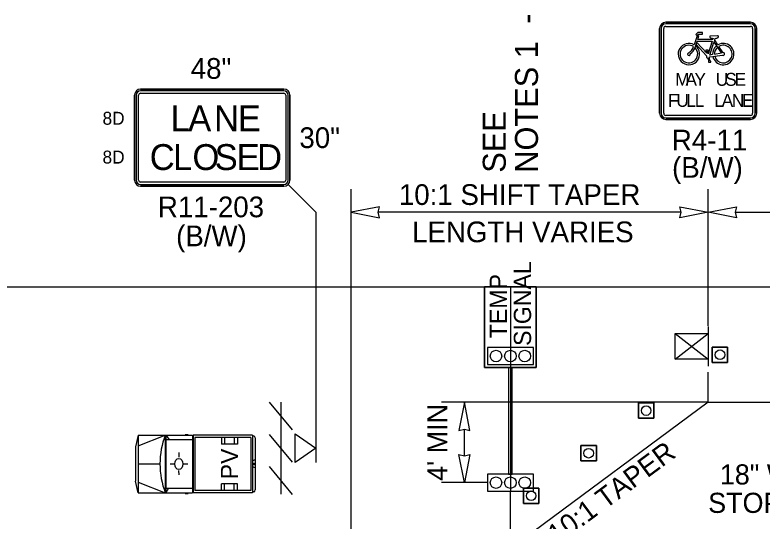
# Model space of a CAD drawing. Extents: x 99977 to 100176, y 99905 to 100011.
# Drawn here: x 100022.4 to 100024.999, y 99977.126 to 99978.886 of the extents above; entities that cross this region are included whole.
import ezdxf

# ---------------------------------------------------------------- set-up
doc = ezdxf.new("R2010")
doc.units = 0
for name, color, linetype in [('RD_ED_ShoulderPavedEdge', 7, 'Continuous'), ('RD_MK_LineEdgeWhite', 7, 'Continuous'), ('TR_SN_ConstructionSigns', 7, 'Continuous'), ('TR_WZ_BarricadeType3', 7, 'Continuous'), ('TR_WZ_PortableSignMount5ftMinBlk-Wht', 7, 'Continuous'), ('TR_WZ_PortableSignMountBlk-Wht', 7, 'Continuous'), ('TR_WZ_ProtectiveVehicle', 7, 'Continuous'), ('TR_WZ_TempSignal', 7, 'Continuous'), ('TR_WZ_TrafficCone', 7, 'Continuous'), ('TR_WZ_WorkZoneDetails', 7, 'Continuous'), ('TR_WZ_WorkZoneTextCurrent', 7, 'Continuous')]:
    doc.layers.add(name, color=color, linetype=linetype)

msp = doc.modelspace()

# ---------------------------------------------------------------- linework, layer by layer
at = {"layer": 'RD_ED_ShoulderPavedEdge'}
msp.add_line((100035.6424, 99977.9393), (100020.3, 99977.9393), dxfattribs=at)
at = {"layer": 'RD_MK_LineEdgeWhite'}
for q in [(100023.5692, 99976.6193), (100035.6425, 99977.5393)]:
    msp.add_line((100024.8112, 99977.5393), q, dxfattribs=at)
at = {"layer": 'TR_SN_ConstructionSigns'}
for p, q in [((100024.6423, 99978.5435), (100024.6423, 99978.8388)), ((100024.6423, 99978.8388), (100024.6423, 99978.5435)), ((100024.6423, 99978.8388), (100024.6423, 99978.5435)), ((100024.648, 99978.8388), (100024.648, 99978.5435)), ((100024.6564, 99978.5435), (100024.6564, 99978.8388)), ((100024.6634, 99978.8599), (100024.9588, 99978.8599)), ((100024.9588, 99978.8599), (100024.6634, 99978.8599)), ((100024.9588, 99978.8599), (100024.6634, 99978.8599)), ((100024.9588, 99978.8543), (100024.6634, 99978.8543)), ((100024.6634, 99978.8458), (100024.9588, 99978.8458)), ((100024.9658, 99978.8388), (100024.9658, 99978.5435)), ((100024.9742, 99978.5435), (100024.9742, 99978.8388)), ((100024.9798, 99978.8388), (100024.9798, 99978.5435)), ((100024.9798, 99978.5435), (100024.9798, 99978.8388)), ((100024.9798, 99978.5435), (100024.9798, 99978.8388)), ((100024.7728, 99978.8131), (100024.7624, 99978.782)), ((100024.7751, 99978.8247), (100024.7681, 99978.8178)), ((100024.7681, 99978.8178), (100024.7728, 99978.8131)), ((100024.775, 99978.8006), (100024.7792, 99978.8131)), ((100024.7916, 99978.8247), (100024.7751, 99978.8247)), ((100024.7752, 99978.8171), (100024.7774, 99978.8192)), ((100024.7792, 99978.8131), (100024.7752, 99978.8171)), ((100024.7774, 99978.8192), (100024.7916, 99978.8192)), ((100024.7916, 99978.8192), (100024.7916, 99978.8247)), ((100024.8435, 99978.8135), (100024.8186, 99978.8118)), ((100024.7676, 99978.7784), (100024.7692, 99978.7831)), ((100024.7692, 99978.7831), (100024.7715, 99978.7902)), ((100024.7692, 99978.7831), (100024.8058, 99978.7433)), ((100024.7715, 99978.7902), (100024.7728, 99978.794)), ((100024.8062, 99978.7526), (100024.7715, 99978.7902)), ((100024.7728, 99978.794), (100024.8254, 99978.794)), ((100024.8276, 99978.8006), (100024.775, 99978.8006)), ((100024.8254, 99978.794), (100024.811, 99978.7507)), ((100024.8164, 99978.7462), (100024.8312, 99978.7904)), ((100024.8288, 99978.804), (100024.8276, 99978.8006)), ((100024.8338, 99978.7983), (100024.8312, 99978.7904)), ((100024.8312, 99978.7904), (100024.8396, 99978.778)), ((100024.8338, 99978.7983), (100024.8357, 99978.8041)), ((100024.845, 99978.7818), (100024.8338, 99978.7983)), ((100024.7676, 99978.7784), (100024.7653, 99978.7717)), ((100024.8115, 99978.7633), (100024.8027, 99978.7633)), ((100024.8049, 99978.76), (100024.8062, 99978.7526)), ((100024.811, 99978.7507), (100024.8093, 99978.76)), ((100024.8093, 99978.76), (100024.8115, 99978.76)), ((100024.8115, 99978.76), (100024.8115, 99978.7633)), ((100024.8396, 99978.778), (100024.8433, 99978.7725)), ((100024.8433, 99978.7725), (100024.8571, 99978.7522)), ((100024.8636, 99978.7544), (100024.8487, 99978.7763)), ((100024.8101, 99978.7352), (100024.8137, 99978.7244)), ((100024.8183, 99978.7244), (100024.8143, 99978.7366)), ((100024.816, 99978.7395), (100024.8273, 99978.7411)), ((100024.8264, 99978.7477), (100024.8164, 99978.7462)), ((100024.8273, 99978.7411), (100024.8338, 99978.7421)), ((100024.8571, 99978.7522), (100024.8329, 99978.7486)), ((100024.8338, 99978.7421), (100024.8601, 99978.746)), ((100024.8137, 99978.7244), (100024.8119, 99978.7244)), ((100024.8119, 99978.7244), (100024.8119, 99978.7211)), ((100024.8119, 99978.7211), (100024.8207, 99978.7211)), ((100024.8207, 99978.7244), (100024.8183, 99978.7244)), ((100024.8207, 99978.7211), (100024.8207, 99978.7244)), ((100022.8369, 99978.6276), (100023.3348, 99978.6276)), ((100023.3348, 99978.6276), (100022.8369, 99978.6276)), ((100023.3348, 99978.6276), (100022.8369, 99978.6276)), ((100022.8159, 99978.3112), (100022.8159, 99978.6065)), ((100022.8159, 99978.6065), (100022.8159, 99978.3112)), ((100022.8159, 99978.6065), (100022.8159, 99978.3112)), ((100022.8215, 99978.6065), (100022.8215, 99978.3112)), ((100022.8299, 99978.3112), (100022.8299, 99978.6065)), ((100023.3348, 99978.622), (100022.8369, 99978.622)), ((100022.8369, 99978.6135), (100023.3348, 99978.6135)), ((100023.3418, 99978.6065), (100023.3418, 99978.3112)), ((100023.3502, 99978.3112), (100023.3502, 99978.6065)), ((100023.3559, 99978.6065), (100023.3559, 99978.3112)), ((100023.3559, 99978.3112), (100023.3559, 99978.6065)), ((100023.3559, 99978.3112), (100023.3559, 99978.6065)), ((100024.9588, 99978.5364), (100024.6634, 99978.5364)), ((100024.6634, 99978.528), (100024.9588, 99978.528)), ((100024.9588, 99978.5224), (100024.6634, 99978.5224)), ((100024.6634, 99978.5224), (100024.9588, 99978.5224)), ((100024.6634, 99978.5224), (100024.9588, 99978.5224)), ((100023.3348, 99978.3042), (100022.8369, 99978.3042)), ((100022.8369, 99978.2957), (100023.3348, 99978.2957)), ((100023.3348, 99978.2901), (100022.8369, 99978.2901)), ((100022.8369, 99978.2901), (100023.3348, 99978.2901)), ((100022.8369, 99978.2901), (100023.3348, 99978.2901))]:
    msp.add_line(p, q, dxfattribs=at)
msp.add_lwpolyline([(100024.8027, 99978.7633), (100024.8027, 99978.76), (100024.8049, 99978.76)], dxfattribs=at)
for centre, radius, start, end in [((100024.6634, 99978.8388), 0.0211, 90, 180), ((100024.6634, 99978.8388), 0.0211, 90, 180), ((100024.6634, 99978.8388), 0.0211, 90, 180), ((100024.6634, 99978.8388), 0.0155, 90, 180), ((100024.6634, 99978.8388), 0.00703, 90, 180), ((100024.9588, 99978.8388), 0.0211, 0, 90), ((100024.9588, 99978.8388), 0.0211, 0, 90), ((100024.9588, 99978.8388), 0.0211, 0, 90), ((100024.9588, 99978.8388), 0.0155, 0, 90), ((100024.9588, 99978.8388), 0.00703, 0, 90), ((100024.8186, 99978.8096), 0.00219, 89.3854, 243.6828), ((100024.8438, 99978.8102), 0.00329, 294.5519, 96.4128), ((100024.7441, 99978.7495), 0.0373, 60.5529, 50.868), ((100024.8636, 99978.7495), 0.0373, 192.9622, 119.9648), ((100024.7441, 99978.7495), 0.0307, 58.1532, 46.1649), ((100024.8636, 99978.7495), 0.0373, 130.0889, 182.8379), ((100024.8636, 99978.7495), 0.0307, 131.3616, 181.6359), ((100024.8636, 99978.7495), 0.0307, 193.937, 119.0598), ((100024.7441, 99978.7495), 0.00493, 105.257, 14.3233), ((100024.8106, 99978.7407), 0.00548, 151.1744, 264.8566), ((100024.8106, 99978.7407), 0.00548, 312.0053, 347.2932), ((100024.8636, 99978.7495), 0.00493, 225.1095, 90.4672), ((100022.8369, 99978.6065), 0.0211, 90, 180), ((100022.8369, 99978.6065), 0.0211, 90, 180), ((100022.8369, 99978.6065), 0.0211, 90, 180), ((100023.3348, 99978.6065), 0.0211, 0, 90), ((100023.3348, 99978.6065), 0.0211, 0, 90), ((100023.3348, 99978.6065), 0.0211, 0, 90), ((100022.8369, 99978.6065), 0.0155, 90, 180), ((100022.8369, 99978.6065), 0.00703, 90, 180), ((100023.3348, 99978.6065), 0.0155, 0, 90), ((100023.3348, 99978.6065), 0.00703, 0, 90), ((100024.6634, 99978.5435), 0.0211, 180, 270), ((100024.6634, 99978.5435), 0.0211, 180, 270), ((100024.6634, 99978.5435), 0.0211, 180, 270), ((100024.6634, 99978.5435), 0.0155, 180, 270), ((100024.6634, 99978.5435), 0.00703, 180, 270), ((100024.9588, 99978.5435), 0.0211, 270, 0), ((100024.9588, 99978.5435), 0.0211, 270, 0), ((100024.9588, 99978.5435), 0.0155, 270, 0), ((100024.9588, 99978.5435), 0.00703, 270, 0), ((100024.9588, 99978.5435), 0.0211, 270, 0), ((100022.8369, 99978.3112), 0.0211, 180, 270), ((100022.8369, 99978.3112), 0.0211, 180, 270), ((100022.8369, 99978.3112), 0.0211, 180, 270), ((100022.8369, 99978.3112), 0.0155, 180, 270), ((100022.8369, 99978.3112), 0.00703, 180, 270), ((100023.3348, 99978.3112), 0.0155, 270, 0), ((100023.3348, 99978.3112), 0.00703, 270, 0), ((100023.3348, 99978.3112), 0.0211, 270, 0), ((100023.3348, 99978.3112), 0.0211, 270, 0), ((100023.3348, 99978.3112), 0.0211, 270, 0)]:
    msp.add_arc(centre, radius, start, end, dxfattribs=at)
for centre, major_axis, ratio, start_param, end_param in [((100024.8317, 99978.8148), (-0.0186, 0), 0.588235, 0.686048, 1.410588), ((100024.8317, 99978.8148), (-0.0186, 0), 0.588235, 1.786993, 2.401245), ((100024.749, 99978.7702), (-0.0105, -0.0158), 0.413554, 0.494612, 2.170849), ((100024.749, 99978.7702), (-0.014, -0.021), 0.55814, 0.868091, 1.989998)]:
    msp.add_ellipse(centre, major_axis=major_axis, ratio=ratio, start_param=start_param, end_param=end_param, dxfattribs=at)
at = {"layer": 'TR_WZ_BarricadeType3'}
for p, q in [((100023.3648, 99977.4429), (100023.2848, 99977.5393)), ((100023.3248, 99977.5389), (100023.3248, 99977.2189)), ((100023.3648, 99977.3307), (100023.2848, 99977.4271)), ((100023.3648, 99977.2184), (100023.2848, 99977.3149))]:
    msp.add_line(p, q, dxfattribs=at)
at = {"layer": 'TR_WZ_PortableSignMount5ftMinBlk-Wht'}
for p, q in [((100024.8112, 99977.8019), (100024.8112, 99977.664)), ((100024.6962, 99977.6881), (100024.8112, 99977.7778)), ((100024.6962, 99977.7778), (100024.8112, 99977.6881)), ((100024.7535, 99977.7328), (100024.7535, 99977.7328)), ((100024.7537, 99977.7329), (100024.7537, 99977.7329))]:
    msp.add_line(p, q, dxfattribs=at)
msp.add_lwpolyline([(100024.6962, 99977.6881), (100024.6962, 99977.7778), (100024.8112, 99977.7778), (100024.8112, 99977.6881)], close=True, dxfattribs=at)
at = {"layer": 'TR_WZ_PortableSignMountBlk-Wht'}
msp.add_line((100023.4466, 99977.4289), (100023.4466, 99977.3289), dxfattribs=at)
msp.add_lwpolyline([(100023.4466, 99977.379), (100023.3748, 99977.3289), (100023.3748, 99977.4289)], close=True, dxfattribs=at)
at = {"layer": 'TR_WZ_ProtectiveVehicle'}
for p, q in [((100022.8282, 99977.4244), (100022.8189, 99977.3841)), ((100022.8282, 99977.4244), (100022.8282, 99977.2244)), ((100022.8282, 99977.4244), (100023.0171, 99977.4244)), ((100022.8282, 99977.3878), (100022.9226, 99977.4244)), ((100022.9226, 99977.4244), (100022.9226, 99977.2244)), ((100022.9244, 99977.4244), (100022.9244, 99977.2244)), ((100022.9244, 99977.4244), (100022.9364, 99977.4089)), ((100022.9244, 99977.4089), (100023.0171, 99977.4089)), ((100022.9913, 99977.4272), (100023.0027, 99977.4272)), ((100023.0171, 99977.4244), (100023.0171, 99977.2244)), ((100023.2256, 99977.4244), (100023.0198, 99977.4244)), ((100023.0198, 99977.4244), (100023.0198, 99977.2244)), ((100023.2197, 99977.4164), (100023.0257, 99977.4164)), ((100023.0257, 99977.4164), (100023.0257, 99977.2324)), ((100023.1184, 99977.4164), (100023.1184, 99977.3934)), ((100023.1284, 99977.4164), (100023.1284, 99977.3934)), ((100023.1624, 99977.4164), (100023.1624, 99977.3934)), ((100023.1734, 99977.4164), (100023.1734, 99977.3934)), ((100023.2197, 99977.4164), (100023.2197, 99977.2324)), ((100023.2256, 99977.4244), (100023.2256, 99977.2244)), ((100023.2307, 99977.4211), (100023.2263, 99977.4211)), ((100023.2263, 99977.4211), (100023.2263, 99977.2277)), ((100023.2352, 99977.415), (100023.2352, 99977.2338)), ((100022.8189, 99977.3841), (100022.8189, 99977.2648)), ((100023.1734, 99977.3934), (100023.1184, 99977.3934)), ((100022.9697, 99977.3641), (100022.9697, 99977.3479)), ((100023.2352, 99977.3385), (100023.2263, 99977.3348)), ((100023.2307, 99977.3272), (100023.2307, 99977.3216)), ((100022.8282, 99977.3244), (100022.9041, 99977.3244)), ((100022.9395, 99977.3246), (100022.9521, 99977.3245)), ((100022.9838, 99977.3241), (100022.9838, 99977.3241)), ((100023.0005, 99977.3237), (100022.9857, 99977.324)), ((100023.2352, 99977.3103), (100023.2263, 99977.3141)), ((100023.2328, 99977.3244), (100023.2287, 99977.3244)), ((100022.9704, 99977.286), (100022.9701, 99977.301)), ((100022.8282, 99977.2244), (100022.8189, 99977.2648)), ((100022.8282, 99977.261), (100022.9226, 99977.2244)), ((100023.1184, 99977.2324), (100023.1184, 99977.2554)), ((100023.1734, 99977.2554), (100023.1184, 99977.2554)), ((100023.1284, 99977.2324), (100023.1284, 99977.2554)), ((100023.1624, 99977.2324), (100023.1624, 99977.2554)), ((100023.1734, 99977.2324), (100023.1734, 99977.2554)), ((100022.8282, 99977.2244), (100023.0171, 99977.2244)), ((100022.9244, 99977.2399), (100023.0171, 99977.2399)), ((100022.9343, 99977.2399), (100022.9244, 99977.2244)), ((100023.2256, 99977.2244), (100023.0198, 99977.2244)), ((100023.2197, 99977.2324), (100023.0257, 99977.2324)), ((100023.2307, 99977.2277), (100023.2263, 99977.2277)), ((100022.9913, 99977.2216), (100023.0027, 99977.2216))]:
    msp.add_line(p, q, dxfattribs=at)
for centre, major_axis, start_param, end_param in [((100023.0576, 99977.3244), (0, -0.2099), 4.215667, 5.208926), ((100023.2307, 99977.415), (0, 0.0061), 4.712389, 6.283185), ((100023.2307, 99977.2338), (0, -0.0061), 0, 1.570796)]:
    msp.add_ellipse(centre, major_axis=major_axis, ratio=0.73155, start_param=start_param, end_param=end_param, dxfattribs=at)
for centre, major_axis in [((100022.9697, 99977.3244), (0, 0.0193)), ((100023.2307, 99977.3244), (0, 0.00282))]:
    msp.add_ellipse(centre, major_axis=major_axis, ratio=0.73155, dxfattribs=at)
at = {"layer": 'TR_WZ_TempSignal'}
for p, q in [((100024.033, 99977.6596), (100024.033, 99977.9397)), ((100024.033, 99977.9397), (100024.2131, 99977.9397)), ((100024.2131, 99977.9397), (100024.033, 99977.9397)), ((100024.033, 99977.9397), (100024.033, 99977.6596)), ((100024.1231, 99977.9397), (100024.1231, 99977.2294)), ((100024.2131, 99977.9397), (100024.2131, 99977.6596)), ((100024.2131, 99977.6596), (100024.2131, 99977.9397)), ((100024.203, 99977.7295), (100024.0432, 99977.7295)), ((100024.0432, 99977.7295), (100024.0432, 99977.6696)), ((100024.203, 99977.6696), (100024.203, 99977.7295)), ((100024.0432, 99977.6696), (100024.203, 99977.6696)), ((100024.2131, 99977.6596), (100024.033, 99977.6596)), ((100024.033, 99977.6596), (100024.1164, 99977.6596)), ((100024.1298, 99977.6596), (100024.1164, 99977.6596)), ((100024.1164, 99977.6596), (100024.1164, 99977.2893)), ((100024.1164, 99977.6596), (100024.1298, 99977.6596)), ((100024.1298, 99977.2893), (100024.1298, 99977.6596)), ((100024.1298, 99977.6596), (100024.2131, 99977.6596)), ((100024.203, 99977.2893), (100024.0432, 99977.2893)), ((100024.0432, 99977.2893), (100024.0432, 99977.2294)), ((100024.1164, 99977.2893), (100024.1298, 99977.2893)), ((100024.203, 99977.2294), (100024.203, 99977.2893)), ((100024.0432, 99977.2294), (100024.203, 99977.2294))]:
    msp.add_line(p, q, dxfattribs=at)
for points in [[(100024.0432, 99977.7295), (100024.0432, 99977.6696), (100024.203, 99977.6696), (100024.203, 99977.7295), (100024.0432, 99977.7295)], [(100024.0432, 99977.2893), (100024.0432, 99977.2294), (100024.203, 99977.2294), (100024.203, 99977.2893), (100024.0432, 99977.2893)]]:
    msp.add_lwpolyline(points, dxfattribs=at)
for centre in [(100024.0731, 99977.6995), (100024.0731, 99977.6995), (100024.1231, 99977.6995), (100024.1231, 99977.6995), (100024.173, 99977.6995), (100024.173, 99977.6995), (100024.0731, 99977.2593), (100024.0731, 99977.2593), (100024.1231, 99977.2593), (100024.1231, 99977.2593), (100024.173, 99977.2593), (100024.173, 99977.2593)]:
    msp.add_circle(centre, 0.02, dxfattribs=at)
at = {"layer": 'TR_WZ_TrafficCone'}
for points in [[(100024.8789, 99977.6773), (100024.8256, 99977.6773), (100024.8256, 99977.7306), (100024.8789, 99977.7306), (100024.8789, 99977.6773)], [(100024.8789, 99977.7306), (100024.8256, 99977.7306), (100024.8256, 99977.6773), (100024.8789, 99977.6773), (100024.8789, 99977.7306)], [(100024.6221, 99977.4832), (100024.5687, 99977.4832), (100024.5687, 99977.5366), (100024.6221, 99977.5366), (100024.6221, 99977.4832)], [(100024.6221, 99977.5366), (100024.5687, 99977.5366), (100024.5687, 99977.4832), (100024.6221, 99977.4832), (100024.6221, 99977.5366)], [(100024.4221, 99977.3351), (100024.3687, 99977.3351), (100024.3687, 99977.3884), (100024.4221, 99977.3884), (100024.4221, 99977.3351)], [(100024.4221, 99977.3884), (100024.3687, 99977.3884), (100024.3687, 99977.3351), (100024.4221, 99977.3351), (100024.4221, 99977.3884)], [(100024.2221, 99977.1869), (100024.1687, 99977.1869), (100024.1687, 99977.2403), (100024.2221, 99977.2403), (100024.2221, 99977.1869)], [(100024.2221, 99977.2403), (100024.1687, 99977.2403), (100024.1687, 99977.1869), (100024.2221, 99977.1869), (100024.2221, 99977.2403)]]:
    msp.add_lwpolyline(points, dxfattribs=at)
for centre in [(100024.8523, 99977.704), (100024.5954, 99977.5099), (100024.3954, 99977.3617), (100024.1954, 99977.2136)]:
    msp.add_circle(centre, 0.0167, dxfattribs=at)
at = {"layer": 'TR_WZ_WorkZoneDetails'}
for p, q in [((100023.3497, 99978.2963), (100023.4466, 99978.1993)), ((100023.5692, 99976.2193), (100023.5692, 99978.2793)), ((100024.8112, 99977.804), (100024.8112, 99978.2793)), ((100023.4466, 99978.1993), (100023.4466, 99977.4289)), ((100024.7175, 99978.1993), (100023.6629, 99978.1993)), ((100024.9049, 99978.1993), (100025.4071, 99978.1993)), ((100024.8112, 99977.5393), (100024.8112, 99977.644)), ((100024.0432, 99977.5393), (100023.8832, 99977.5393)), ((100024.8112, 99977.5393), (100024.0432, 99977.5393)), ((100023.9632, 99977.353), (100023.9632, 99977.4456)), ((100024.0432, 99977.2593), (100023.8832, 99977.2593)), ((100024.1231, 99974.9817), (100024.1231, 99977.2294))]:
    msp.add_line(p, q, dxfattribs=at)
for points in [[(100023.5692, 99978.1993), (100023.6675, 99978.18), (100023.6629, 99978.1993), (100023.6675, 99978.2186)], [(100024.8112, 99978.1993), (100024.7129, 99978.18), (100024.7175, 99978.1993), (100024.7129, 99978.2186)], [(100024.8112, 99978.1993), (100024.9095, 99978.2186), (100024.9049, 99978.1993), (100024.9095, 99978.18)], [(100023.9632, 99977.5393), (100023.9439, 99977.441), (100023.9632, 99977.4456), (100023.9825, 99977.441)], [(100023.9632, 99977.2593), (100023.9439, 99977.3576), (100023.9632, 99977.353), (100023.9825, 99977.3576)]]:
    msp.add_lwpolyline(points, close=True, dxfattribs=at)

# ---------------------------------------------------------------- texts
at = {"layer": 'TR_SN_ConstructionSigns'}
for s, p in [('48"', (100023.0111, 99978.6636)), ('30"', (100023.3891, 99978.4228)), ('R4-11', (100024.6848, 99978.4144)), ('(B/W)', (100024.6856, 99978.3193)), ('R11-203', (100022.8969, 99978.1821)), ('(B/W)', (100022.9603, 99978.0813))]:
    msp.add_text(s, height=0.072, rotation=360, dxfattribs=at).set_placement(p)
for s, height, p in [('M', 0.045, (100024.6961, 99978.6391)), ('A', 0.045, (100024.7321, 99978.6391)), ('Y', 0.045, (100024.7636, 99978.6391)), ('U', 0.045, (100024.8374, 99978.6391)), ('S', 0.045, (100024.8703, 99978.6391)), ('E', 0.045, (100024.9031, 99978.6391)), ('F', 0.045, (100024.6709, 99978.566)), ('U', 0.045, (100024.7002, 99978.566)), ('L', 0.045, (100024.7353, 99978.566)), ('L', 0.045, (100024.7645, 99978.566)), ('L', 0.045, (100024.8325, 99978.566)), ('A', 0.045, (100024.8581, 99978.566)), ('N', 0.045, (100024.8932, 99978.566)), ('E', 0.045, (100024.9283, 99978.566)), ('8D', 0.045, (100022.7043, 99978.5038)), ('L', 0.09, (100022.941, 99978.4813)), ('A', 0.09, (100023.0022, 99978.4813)), ('N', 0.09, (100023.0922, 99978.4813)), ('E', 0.09, (100023.175, 99978.4813)), ('C', 0.09, (100022.8685, 99978.3463)), ('L', 0.09, (100022.9495, 99978.3463)), ('O', 0.09, (100023.017, 99978.3463)), ('S', 0.09, (100023.0944, 99978.3463)), ('E', 0.09, (100023.1709, 99978.3463)), ('D', 0.09, (100023.242, 99978.3463)), ('8D', 0.045, (100022.7043, 99978.3688))]:
    msp.add_text(s, height=height, dxfattribs=at).set_placement(p)
at = {"layer": 'TR_WZ_ProtectiveVehicle'}
msp.add_text('PV', height=0.06, rotation=90, dxfattribs=at).set_placement((100023.1759, 99977.2707))
at = {"layer": 'TR_WZ_TempSignal'}
for s, p in [('SIGNAL', (100024.1951, 99977.7346)), ('TEMP', (100024.1111, 99977.7617))]:
    msp.add_text(s, height=0.06, rotation=90, dxfattribs=at).set_placement(p)
at = {"layer": 'TR_WZ_WorkZoneTextCurrent'}
for s, height, rotation, p in [('-', 0.08, 90, (100024.2191, 99978.8547)), ('NOTES 1', 0.08, 90, (100024.2191, 99978.3369)), ('SEE', 0.08, 90, (100024.1071, 99978.3369)), ("4' MIN", 0.07, 90, (100023.9039, 99977.2654)), ('10:1 TAPER', 0.07, 36.5289, (100024.2858, 99977.0415))]:
    msp.add_text(s, height=height, rotation=rotation, dxfattribs=at).set_placement(p)
for s, height, p in [('10:1 SHIFT TAPER', 0.072, (100023.7352, 99978.2249)), ('LENGTH VARIES', 0.072, (100023.7813, 99978.0953)), ('18" WHITE', 0.07, (100024.8518, 99977.2529)), ('STOP BAR', 0.07, (100024.8112, 99977.1541))]:
    msp.add_text(s, height=height, dxfattribs=at).set_placement(p)

doc.saveas('drawing.dxf')
